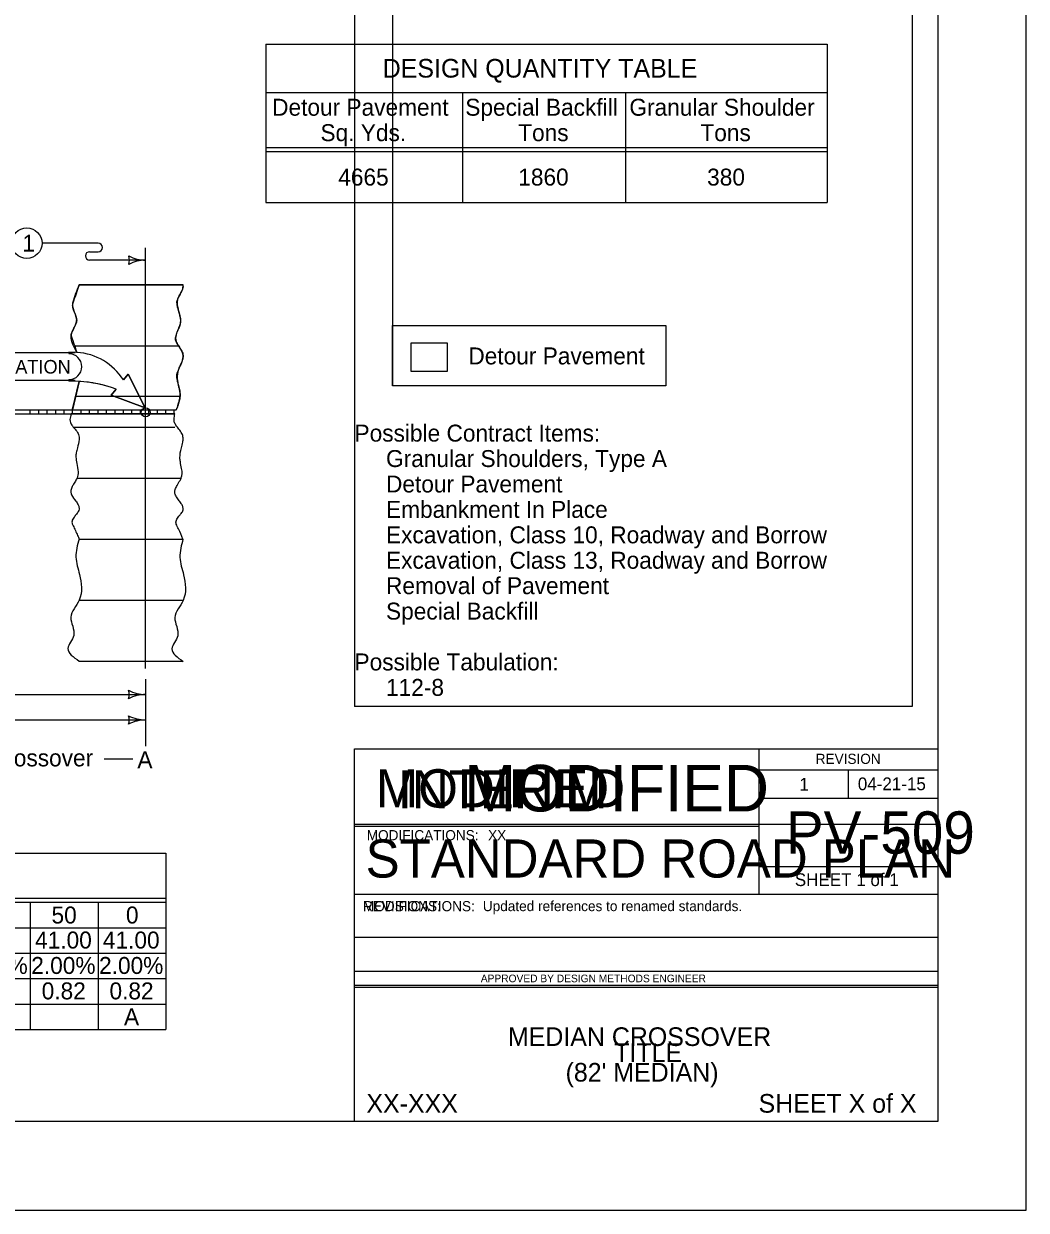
# Model space of a CAD drawing. Extents: x -2135039 to -2131695, y -2139150 to -2136566.
# Drawn here: x -2132878 to -2131695, y -2139150 to -2137750 of the extents above; entities that cross this region are included whole.
import ezdxf

# ---------------------------------------------------------------- set-up
doc = ezdxf.new("R2010")
doc.units = 0
for name, color, linetype in [('dsnDOTLogo', 7, 'Continuous'), ('dsnNonPlotable', 7, 'Continuous'), ('dsnStdBlock', 7, 'Continuous'), ('dsnstdblockInterim', 7, 'Continuous'), ('dsnStdDimension', 7, 'Continuous'), ('dsnStdLabel', 7, 'Continuous'), ('dsnStdLineDrawingWt4', 7, 'Continuous'), ('dsnStdLogo', 7, 'Continuous'), ('dsnstdModifiedBlock', 7, 'Continuous'), ('dsnStdShading', 7, 'Continuous'), ('Level 1', 7, 'Continuous'), ('Level 10', 7, 'Continuous'), ('Level 11', 7, 'Continuous'), ('Level 12', 7, 'Continuous'), ('Level 2', 7, 'Continuous'), ('Level 3', 7, 'Continuous'), ('Level 6', 7, 'Continuous'), ('Level 7', 7, 'Continuous'), ('Level 9', 7, 'Continuous')]:
    doc.layers.add(name, color=color, linetype=linetype)

msp = doc.modelspace()

# ---------------------------------------------------------------- linework, layer by layer
at = {"layer": 'dsnDOTLogo'}
msp.add_lwpolyline([(-2135038.9, -2139150.4), (-2131694.9, -2139150.4), (-2131694.9, -2136566.4), (-2135038.9, -2136566.4)], close=True, dxfattribs=at)
at = {"layer": 'dsnNonPlotable'}
for p, q in [((-2132487.5, -2137085.9), (-2132487.5, -2138555.9)), ((-2131829.4, -2137085.9), (-2131829.4, -2138555.9)), ((-2132442.5, -2137185.9), (-2132442.5, -2138177.5)), ((-2131829.4, -2138555.9), (-2132487.5, -2138555.9))]:
    msp.add_line(p, q, dxfattribs=at)
at = {"layer": 'dsnStdDimension'}
for p, q in [((-2132790, -2138009.4), (-2132856.2, -2138009.4)), ((-2132800, -2138019.4), (-2132790, -2138019.4)), ((-2132733.9, -2138029.4), (-2132800, -2138029.4)), ((-2132734, -2138523.8), (-2132734, -2138602.7)), ((-2132955.1, -2138541.9), (-2132734, -2138541.9)), ((-2133686.9, -2138571.9), (-2132734, -2138571.9)), ((-2132782.7, -2138617.7), (-2132749, -2138617.7))]:
    msp.add_line(p, q, dxfattribs=at)
msp.add_circle((-2132733.9, -2138209.1), 5.33, dxfattribs=at)
for centre, radius, start, end in [((-2132790, -2138014.4), 5, 270, 90), ((-2132800, -2138024.4), 5, 90, 270), ((-2132769.5, -2138029.4), 16.4, 342.2666, 17.7333), ((-2132733.9, -2137986.9), 42.5, 241.9275, 270), ((-2132733.9, -2138071.9), 42.5, 90, 118.0725), ((-2132769.7, -2138541.9), 16.4, 342.2666, 17.7333), ((-2132734, -2138499.4), 42.5, 241.9275, 270), ((-2132734, -2138584.4), 42.5, 90, 118.0725), ((-2132769.7, -2138571.9), 16.4, 342.2666, 17.7333), ((-2132734, -2138529.4), 42.5, 241.9275, 270), ((-2132734, -2138614.4), 42.5, 90, 118.0725)]:
    msp.add_arc(centre, radius, start, end, dxfattribs=at)
at = {"layer": 'dsnStdLabel'}
for p, q in [((-2132817, -2138138.8), (-2133024.5, -2138138.8)), ((-2132815.1, -2138138.3), (-2132824.6, -2138137.9)), ((-2132824.6, -2138137.9), (-2132824.6, -2138139.7)), ((-2132817, -2138171.3), (-2133024.6, -2138171.3)), ((-2132824.6, -2138170.4), (-2132824.6, -2138172.2)), ((-2132754.6, -2138163.8), (-2132760.2, -2138170.8)), ((-2132734.6, -2138203.8), (-2132754.6, -2138163.8)), ((-2132768.7, -2138181.5), (-2132774.6, -2138188.8)), ((-2132774.6, -2138188.8), (-2132734.6, -2138203.8))]:
    msp.add_line(p, q, dxfattribs=at)
for centre, radius, start, end in [((-2132824.6, -2138155.1), 15.3, 270, 90), ((-2132819.6, -2138208.5), 70.4, 32.3953, 86.3054), ((-2132821.8, -2138328.3), 156.1, 70.133, 91.0368)]:
    msp.add_arc(centre, radius, start, end, dxfattribs=at)
at = {"layer": 'dsnStdLineDrawingWt4'}
for p, q in [((-2132812.4, -2138058.5), (-2132689.9, -2138058.5)), ((-2132817.8, -2138130.5), (-2132695.2, -2138130.5)), ((-2132820.1, -2138205.4), (-2132812.3, -2138172.5)), ((-2132816.7, -2138189.7), (-2132694.1, -2138189.7)), ((-2133025.8, -2138206.1), (-2132697.8, -2138206.1)), ((-2133025.8, -2138210.9), (-2132699.5, -2138210.9)), ((-2132870.1, -2138210.9), (-2132870.1, -2138206.1)), ((-2132860.1, -2138210.9), (-2132860.1, -2138206.1)), ((-2132850.1, -2138210.9), (-2132850.1, -2138206.1)), ((-2132840.1, -2138210.9), (-2132840.1, -2138206.1)), ((-2132830.1, -2138210.9), (-2132830.1, -2138206.1)), ((-2132820.1, -2138210.9), (-2132820.1, -2138206.1)), ((-2132810.1, -2138210.9), (-2132810.1, -2138206.1)), ((-2132800.1, -2138210.9), (-2132800.1, -2138206.1)), ((-2132790.1, -2138210.9), (-2132790.1, -2138206.1)), ((-2132780.1, -2138210.9), (-2132780.1, -2138206.1)), ((-2132770.1, -2138210.9), (-2132770.1, -2138206.1)), ((-2132760.1, -2138210.9), (-2132760.1, -2138206.1)), ((-2132750.1, -2138210.9), (-2132750.1, -2138206.1)), ((-2132740.1, -2138210.9), (-2132740.1, -2138206.1)), ((-2132730.1, -2138210.9), (-2132730.1, -2138206.1)), ((-2132720.1, -2138210.9), (-2132720.1, -2138206.1)), ((-2132710.1, -2138210.9), (-2132710.1, -2138206.1)), ((-2132700.1, -2138210.9), (-2132700.1, -2138206.1)), ((-2132818.3, -2138226.5), (-2132699.5, -2138226.5)), ((-2132814.9, -2138286.5), (-2132693, -2138286.5)), ((-2132812.4, -2138358.5), (-2132689.9, -2138358.5)), ((-2132812.4, -2138502.5), (-2132690, -2138502.5))]:
    msp.add_line(p, q, dxfattribs=at)
for points in [[(-2132815, -2138138.4), (-2132821.8, -2138118.9), (-2132821.3, -2138115.7), (-2132818.6, -2138109.7), (-2132816.2, -2138104.6), (-2132815.3, -2138099.8), (-2132816.2, -2138095.6), (-2132819, -2138088), (-2132820.1, -2138082.7), (-2132819.4, -2138078.7), (-2132812.4, -2138058.5)], [(-2132689.7, -2138060.3), (-2132690, -2138062.1), (-2132692.3, -2138067.6), (-2132696.2, -2138075.6), (-2132696.9, -2138080.5), (-2132695.7, -2138087), (-2132694.4, -2138091.5), (-2132692.8, -2138098.6), (-2132693.8, -2138106.6), (-2132695.5, -2138111), (-2132698.5, -2138119.9), (-2132697.4, -2138126.6), (-2132694.9, -2138130.9), (-2132692.1, -2138135.5), (-2132689.9, -2138140.7), (-2132689.9, -2138144.7), (-2132691.8, -2138150.8), (-2132692.6, -2138152.7), (-2132695.9, -2138160.6), (-2132696.4, -2138171.9), (-2132695.1, -2138177.3), (-2132693.7, -2138183.5), (-2132693.5, -2138191.6), (-2132694.8, -2138197.1), (-2132696.6, -2138202.8)], [(-2132689.7, -2138060.3), (-2132689.7, -2138059.2), (-2132689.8, -2138058.7), (-2132689.9, -2138058.5)], [(-2132696.5, -2138202.8), (-2132697.2, -2138204.6), (-2132697.8, -2138206.1)], [(-2132821.7, -2138210.9), (-2132823.2, -2138217.5), (-2132822.7, -2138220.9), (-2132820.3, -2138225), (-2132816.2, -2138230.1), (-2132813, -2138235.3), (-2132812.5, -2138241), (-2132814.5, -2138250.8), (-2132815.9, -2138256.9), (-2132816.2, -2138261.7), (-2132815.2, -2138269.3), (-2132813.7, -2138279.2), (-2132813.8, -2138283.1), (-2132816.2, -2138289.1), (-2132819, -2138293.8), (-2132821, -2138297.6), (-2132822.2, -2138302.6), (-2132821.3, -2138306.3), (-2132816.4, -2138313.7), (-2132813.6, -2138318.1), (-2132812.5, -2138321.6), (-2132812.9, -2138324.8), (-2132815.5, -2138329.1), (-2132818.3, -2138332.6), (-2132820, -2138335.1), (-2132820.8, -2138337.4), (-2132820.7, -2138339.6), (-2132819.4, -2138342.8), (-2132816.9, -2138348.3), (-2132814.2, -2138354.4), (-2132812.4, -2138358.5)], [(-2132689.9, -2138358.5), (-2132695.2, -2138346.5), (-2132697.8, -2138340.8), (-2132698.2, -2138338.5), (-2132696.4, -2138334), (-2132694.6, -2138331.6), (-2132692, -2138328.2), (-2132689.8, -2138324), (-2132690.2, -2138320.1), (-2132692, -2138316.6), (-2132695.1, -2138312.1), (-2132698.1, -2138307.7), (-2132699.5, -2138303.5), (-2132699.1, -2138300.1), (-2132696.8, -2138295.1), (-2132693.4, -2138289.3), (-2132691.9, -2138286), (-2132691, -2138281.8), (-2132691.5, -2138275.3), (-2132693, -2138267.3), (-2132693.5, -2138262.6), (-2132691.8, -2138251), (-2132690.2, -2138244.2), (-2132689.7, -2138239), (-2132691.2, -2138233.9), (-2132694.7, -2138228.9), (-2132698.3, -2138224), (-2132700.2, -2138220), (-2132700.4, -2138217.2), (-2132699.5, -2138210.9)], [(-2132812.4, -2138358.5), (-2132816.2, -2138379.7), (-2132811.9, -2138400.3), (-2132812.4, -2138430.5), (-2132822.2, -2138450.8), (-2132818.8, -2138472.2), (-2132825.6, -2138487.6), (-2132812.4, -2138502.5)], [(-2132689.9, -2138358.5), (-2132693.5, -2138380.1), (-2132689.2, -2138400.6), (-2132689.7, -2138430.8), (-2132699.5, -2138451.1), (-2132696.1, -2138472.5), (-2132702.9, -2138487.9), (-2132689.7, -2138502.8)]]:
    msp.add_spline(points, degree=3, dxfattribs=at)
at = {"layer": 'dsnStdLogo'}
for p, q in [((-2132010.4, -2138605.9), (-2132010.4, -2138697.3)), ((-2132010.4, -2138630.9), (-2131799.4, -2138630.9)), ((-2131904.9, -2138630.9), (-2131904.9, -2138664.1)), ((-2132010.4, -2138664.1), (-2131799.4, -2138664.1)), ((-2132487.5, -2138697.3), (-2132010.4, -2138697.3)), ((-2132010.4, -2138697.3), (-2132010.4, -2138777.3)), ((-2131799.4, -2138745.1), (-2132010.4, -2138745.1)), ((-2132487.5, -2138777.3), (-2131799.4, -2138777.3)), ((-2132487.5, -2138828.3), (-2131799.4, -2138828.3)), ((-2132487.5, -2138868.3), (-2131799.4, -2138868.3)), ((-2132487.5, -2138887.3), (-2131799.4, -2138887.3))]:
    msp.add_line(p, q, dxfattribs=at)
msp.add_lwpolyline([(-2132487.5, -2138605.9), (-2131799.4, -2138605.9), (-2131799.4, -2139045.9), (-2132487.5, -2139045.9)], close=True, dxfattribs=at)
at = {"layer": 'dsnstdModifiedBlock'}
for p, q in [((-2132487.5, -2138695), (-2131799.4, -2138695)), ((-2132487.5, -2138885), (-2131799.4, -2138885))]:
    msp.add_line(p, q, dxfattribs=at)
msp.add_lwpolyline([(-2132487.5, -2138605.9), (-2131799.4, -2138605.9), (-2131799.4, -2139045.9), (-2132487.5, -2139045.9)], close=True, dxfattribs=at)
at = {"layer": 'dsnStdShading'}
for p, q in [((-2132689.9, -2138058.5), (-2132812.4, -2138058.5)), ((-2132420.7, -2138126.9), (-2132378.1, -2138126.9)), ((-2132420.7, -2138160.6), (-2132420.7, -2138126.9)), ((-2132378.1, -2138126.9), (-2132378.1, -2138160.6)), ((-2132378.1, -2138160.6), (-2132420.7, -2138160.6)), ((-2132812.3, -2138172.5), (-2132820.3, -2138206.1)), ((-2132760.2, -2138170.8), (-2132754.6, -2138163.8)), ((-2132754.6, -2138163.8), (-2132734.6, -2138203.8)), ((-2132774.6, -2138188.8), (-2132768.7, -2138181.5)), ((-2132734.6, -2138203.8), (-2132774.6, -2138188.8)), ((-2132812.4, -2138358.5), (-2132689.9, -2138358.5))]:
    msp.add_line(p, q, dxfattribs=at)
for points in [[(-2132699.5, -2138210.9), (-2132700.1, -2138210.9), (-2132710.1, -2138210.9), (-2132720.1, -2138210.9), (-2132730.1, -2138210.9), (-2132740.1, -2138210.9), (-2132750.1, -2138210.9), (-2132760.1, -2138210.9), (-2132770.1, -2138210.9), (-2132780.1, -2138210.9), (-2132790.1, -2138210.9), (-2132800.1, -2138210.9), (-2132810.1, -2138210.9), (-2132820.1, -2138210.9), (-2132821.7, -2138210.9)], [(-2132820.3, -2138206.1), (-2132820.1, -2138206.1), (-2132810.1, -2138206.1), (-2132800.1, -2138206.1), (-2132790.1, -2138206.1), (-2132780.1, -2138206.1), (-2132770.1, -2138206.1), (-2132760.1, -2138206.1), (-2132750.1, -2138206.1), (-2132740.1, -2138206.1), (-2132730.1, -2138206.1), (-2132720.1, -2138206.1), (-2132710.1, -2138206.1), (-2132700.1, -2138206.1), (-2132697.8, -2138206.1)]]:
    msp.add_lwpolyline(points, dxfattribs=at)
for centre, radius, start, end in [((-2132819.6, -2138208.5), 70.4, 32.3953, 86.258), ((-2132821.8, -2138328.3), 156.1, 70.133, 86.5437)]:
    msp.add_arc(centre, radius, start, end, dxfattribs=at)
for points in [[(-2132812.4, -2138058.5), (-2132814.7, -2138065.2), (-2132817.1, -2138072), (-2132819.4, -2138078.7), (-2132819.9, -2138080), (-2132820.2, -2138081.4), (-2132820.1, -2138082.7), (-2132820.1, -2138084.5), (-2132819.5, -2138086.3), (-2132819, -2138088), (-2132818.2, -2138090.6), (-2132817, -2138093), (-2132816.2, -2138095.6), (-2132815.7, -2138097), (-2132815.4, -2138098.4), (-2132815.3, -2138099.8), (-2132815.3, -2138101.4), (-2132815.5, -2138103), (-2132816.2, -2138104.6), (-2132817, -2138106.4), (-2132817.8, -2138108), (-2132818.6, -2138109.7), (-2132819.6, -2138111.7), (-2132820.5, -2138113.7), (-2132821.3, -2138115.7), (-2132821.8, -2138116.7), (-2132822.1, -2138117.9), (-2132821.8, -2138118.9), (-2132819.5, -2138125.4), (-2132817.3, -2138131.8), (-2132815, -2138138.3)], [(-2132696.5, -2138202.8), (-2132696, -2138200.9), (-2132695.4, -2138199), (-2132694.8, -2138197.1), (-2132694.3, -2138195.3), (-2132693.8, -2138193.4), (-2132693.5, -2138191.6), (-2132693, -2138188.9), (-2132693.2, -2138186.1), (-2132693.7, -2138183.5), (-2132694.1, -2138181.4), (-2132694.6, -2138179.3), (-2132695.1, -2138177.3), (-2132695.5, -2138175.5), (-2132696, -2138173.7), (-2132696.4, -2138171.9), (-2132697.2, -2138168.2), (-2132697.3, -2138164.1), (-2132695.9, -2138160.6), (-2132694.8, -2138158), (-2132693.7, -2138155.3), (-2132692.6, -2138152.7), (-2132692.3, -2138152.1), (-2132692, -2138151.4), (-2132691.8, -2138150.8), (-2132690.9, -2138148.8), (-2132690.4, -2138146.8), (-2132689.9, -2138144.7), (-2132689.6, -2138143.4), (-2132689.6, -2138142), (-2132689.9, -2138140.7), (-2132690.4, -2138138.9), (-2132691.1, -2138137.1), (-2132692.1, -2138135.5), (-2132693, -2138134), (-2132694, -2138132.5), (-2132694.9, -2138130.9), (-2132695.8, -2138129.5), (-2132696.6, -2138128.1), (-2132697.4, -2138126.6), (-2132698.5, -2138124.5), (-2132699.1, -2138122), (-2132698.5, -2138119.9), (-2132697.7, -2138116.9), (-2132696.6, -2138113.9), (-2132695.5, -2138111), (-2132695, -2138109.5), (-2132694.3, -2138108.1), (-2132693.8, -2138106.6), (-2132692.9, -2138104), (-2132692.4, -2138101.2), (-2132692.8, -2138098.6), (-2132693.2, -2138096.2), (-2132693.7, -2138093.9), (-2132694.4, -2138091.5), (-2132694.8, -2138090), (-2132695.3, -2138088.5), (-2132695.7, -2138087), (-2132696.3, -2138084.8), (-2132696.7, -2138082.6), (-2132696.9, -2138080.5), (-2132697.1, -2138078.9), (-2132696.9, -2138077.2), (-2132696.2, -2138075.6), (-2132695, -2138072.7), (-2132693.5, -2138070.3), (-2132692.3, -2138067.6), (-2132691.5, -2138065.8), (-2132690.3, -2138064.1), (-2132690, -2138062.1), (-2132689.9, -2138061.5), (-2132689.8, -2138060.9), (-2132689.7, -2138060.3)], [(-2132697.8, -2138206.1), (-2132697.6, -2138205.6), (-2132697.4, -2138205.1), (-2132697.2, -2138204.6), (-2132697, -2138204), (-2132696.8, -2138203.4), (-2132696.5, -2138202.8)]]:
    msp.add_open_spline(points, degree=3, dxfattribs=at)
for points in [[(-2132689.7, -2138060.3), (-2132689.7, -2138059.2), (-2132689.8, -2138058.7), (-2132689.9, -2138058.5)], [(-2132821.7, -2138210.9), (-2132823.2, -2138217.5), (-2132822.7, -2138220.9), (-2132820.3, -2138225), (-2132816.2, -2138230.1), (-2132813, -2138235.3), (-2132812.5, -2138241), (-2132814.5, -2138250.8), (-2132815.9, -2138256.9), (-2132816.2, -2138261.7), (-2132815.2, -2138269.3), (-2132813.7, -2138279.2), (-2132813.8, -2138283.1), (-2132816.2, -2138289.1), (-2132819, -2138293.8), (-2132821, -2138297.6), (-2132822.2, -2138302.6), (-2132821.3, -2138306.3), (-2132816.4, -2138313.7), (-2132813.6, -2138318.1), (-2132812.5, -2138321.6), (-2132812.9, -2138324.8), (-2132815.5, -2138329.1), (-2132818.3, -2138332.6), (-2132820, -2138335.1), (-2132820.8, -2138337.4), (-2132820.7, -2138339.6), (-2132819.4, -2138342.8), (-2132816.9, -2138348.3), (-2132814.2, -2138354.4), (-2132812.4, -2138358.5)], [(-2132689.9, -2138358.5), (-2132695.2, -2138346.5), (-2132697.8, -2138340.8), (-2132698.2, -2138338.5), (-2132696.4, -2138334), (-2132694.6, -2138331.6), (-2132692, -2138328.2), (-2132689.8, -2138324), (-2132690.2, -2138320.1), (-2132692, -2138316.6), (-2132695.1, -2138312.1), (-2132698.1, -2138307.7), (-2132699.5, -2138303.5), (-2132699.1, -2138300.1), (-2132696.8, -2138295.1), (-2132693.4, -2138289.3), (-2132691.9, -2138286), (-2132691, -2138281.8), (-2132691.5, -2138275.3), (-2132693, -2138267.3), (-2132693.5, -2138262.6), (-2132691.8, -2138251), (-2132690.2, -2138244.2), (-2132689.7, -2138239), (-2132691.2, -2138233.9), (-2132694.7, -2138228.9), (-2132698.3, -2138224), (-2132700.2, -2138220), (-2132700.4, -2138217.2), (-2132699.5, -2138210.9)]]:
    msp.add_spline(points, degree=3, dxfattribs=at)
at = {"layer": 'Level 1'}
msp.add_line((-2132592.2, -2137831.6), (-2131930, -2137831.6), dxfattribs=at)
msp.add_lwpolyline([(-2134934.4, -2137035.9), (-2131799.4, -2137035.9), (-2131799.4, -2139045.9), (-2134934.4, -2139045.9)], close=True, dxfattribs=at)
at = {"layer": 'Level 10'}
msp.add_circle((-2132874.2, -2138009.4), 18, dxfattribs=at)
at = {"layer": 'Level 11'}
for p, q in [((-2134872.5, -2138729.1), (-2132710.1, -2138729.1)), ((-2132710.1, -2138729.1), (-2132710.1, -2138937.1)), ((-2134872.5, -2138937.1), (-2132710.1, -2138937.1))]:
    msp.add_line(p, q, dxfattribs=at)
at = {"layer": 'Level 12'}
for p, q in [((-2132592.2, -2137774.4), (-2132592.2, -2137961.4)), ((-2132592.2, -2137774.4), (-2131930, -2137774.4)), ((-2131930, -2137774.4), (-2131930, -2137961.4)), ((-2132592.2, -2137961.4), (-2131930, -2137961.4))]:
    msp.add_line(p, q, dxfattribs=at)
msp.add_lwpolyline([(-2132442.5, -2138106.6), (-2132120.3, -2138106.6), (-2132120.3, -2138177.5), (-2132442.5, -2138177.5)], close=True, dxfattribs=at)
at = {"layer": 'Level 2'}
for p, q in [((-2132360.1, -2137831.6), (-2132360.1, -2137961.4)), ((-2132167.7, -2137831.6), (-2132167.7, -2137961.4)), ((-2132167.7, -2137831.6), (-2132167.7, -2137961.4)), ((-2132592.2, -2137896.4), (-2131930, -2137896.4)), ((-2132592.2, -2137901.4), (-2131930, -2137901.4)), ((-2132420.7, -2138126.9), (-2132378.1, -2138126.9)), ((-2132420.7, -2138160.6), (-2132420.7, -2138126.9)), ((-2132378.1, -2138126.9), (-2132378.1, -2138160.6)), ((-2132378.1, -2138160.6), (-2132420.7, -2138160.6)), ((-2134872.5, -2138782.1), (-2132710.1, -2138782.1)), ((-2134872.5, -2138787.1), (-2132710.1, -2138787.1)), ((-2132870.1, -2138787.1), (-2132870.1, -2138937.1)), ((-2132790.1, -2138787.1), (-2132790.1, -2138937.1))]:
    msp.add_line(p, q, dxfattribs=at)
at = {"layer": 'Level 3'}
for p, q in [((-2132734, -2138511.4), (-2132734, -2138014.9)), ((-2132812.4, -2138430.5), (-2132689.6, -2138430.5))]:
    msp.add_line(p, q, dxfattribs=at)
at = {"layer": 'Level 9'}
for p, q in [((-2134872.5, -2138817.1), (-2132710.1, -2138817.1)), ((-2134872.5, -2138847.1), (-2132710.1, -2138847.1)), ((-2134872.5, -2138877.1), (-2132710.1, -2138877.1)), ((-2134872.5, -2138907.1), (-2132710.1, -2138907.1))]:
    msp.add_line(p, q, dxfattribs=at)

# ---------------------------------------------------------------- texts
at = {"layer": 'dsnNonPlotable'}
msp.add_text('REVISIONS:', height=12, dxfattribs=at).set_placement((-2132477.5, -2138797.6))
at = {"layer": 'dsnStdBlock'}
for s, height, p in [('MODIFIED', 45, (-2132462.4, -2138675.1)), ('MODIFICATIONS:', 12, (-2132477.5, -2138797.6))]:
    msp.add_text(s, height=height, dxfattribs=at).set_placement(p)
at = {"layer": 'dsnstdblockInterim'}
msp.add_text('INTERIM', height=45, dxfattribs=at).set_placement((-2132436.5, -2138676.3))
at = {"layer": 'dsnStdLabel'}
msp.add_text('LOCATION STATION', height=16, dxfattribs=at).set_placement((-2133030.4, -2138163.2))
at = {"layer": 'dsnStdLogo'}
for s, height, p in [('REVISION', 12, (-2131943.4, -2138623.8)), ('04-21-15', 15, (-2131893.7, -2138654.8)), ('1', 15, (-2131962.6, -2138655.3)), ('PV-509', 50, (-2131978.6, -2138729.8)), ('STANDARD ROAD PLAN', 45.001, (-2132474.4, -2138757.9)), ('SHEET 1 of 1', 15, (-2131968, -2138767.9)), ('Updated references to renamed standards.', 12, (-2132336.1, -2138797.5)), ('APPROVED BY DESIGN METHODS ENGINEER', 9.003, (-2132338.5, -2138881.4)), ('MEDIAN CROSSOVER', 22, (-2132306.5, -2138956.6)), ("(82' MEDIAN)", 22, (-2132238.5, -2138998.6))]:
    msp.add_text(s, height=height, dxfattribs=at).set_placement(p)
at = {"layer": 'dsnstdModifiedBlock'}
for s, height, p in [('MODIFIED', 55, (-2132358.1, -2138679.9)), ('MODIFICATIONS:', 12, (-2132473.1, -2138713.9)), ('XX', 12, (-2132329.9, -2138713.9)), ('TITLE', 22, (-2132181.1, -2138975.4)), ('XX-XXX', 22, (-2132473.5, -2139035.3)), ('SHEET X of X', 22, (-2132010.8, -2139035.3))]:
    msp.add_text(s, height=height, dxfattribs=at).set_placement(p)
at = {"layer": 'Level 1'}
for s, p in [('Possible Contract Items:', (-2132487.5, -2138243.5)), ('     Granular Shoulders, Type A', (-2132487.5, -2138273.5)), ('     Detour Pavement', (-2132487.5, -2138303.5)), ('     Embankment In Place', (-2132487.5, -2138333.5)), ('     Excavation, Class 10, Roadway and Borrow', (-2132487.5, -2138363.5)), ('     Excavation, Class 13, Roadway and Borrow', (-2132487.5, -2138393.5)), ('     Removal of Pavement', (-2132487.5, -2138423.5)), ('     Special Backfill', (-2132487.5, -2138453.5)), ('Possible Tabulation:', (-2132487.5, -2138513.5)), ('     112-8', (-2132487.5, -2138543.5))]:
    msp.add_text(s, height=20, dxfattribs=at).set_placement(p)
at = {"layer": 'Level 6'}
msp.add_text('DESIGN QUANTITY TABLE', height=22, dxfattribs=at).set_placement((-2132454.2, -2137814))
at = {"layer": 'Level 7'}
for s, p in [('Detour Pavement', (-2132584.7, -2137859)), ('Special Backfill', (-2132356.8, -2137859)), ('Granular Shoulder', (-2132163.2, -2137859)), ('Sq. Yds.', (-2132527.7, -2137889)), ('Tons', (-2132294.4, -2137889)), ('Tons', (-2132079.4, -2137889)), ('4665', (-2132506.7, -2137941.4)), ('1860', (-2132294.3, -2137941.4)), ('380', (-2132071.5, -2137941.4)), ('1', (-2132879.4, -2138019.4)), ('Detour Pavement', (-2132353.2, -2138152.4)), (' of Crossover', (-2132954.9, -2138626.7)), ('A', (-2132743.7, -2138628.9)), ('50', (-2132845, -2138812.1)), ('0', (-2132757.2, -2138812.1)), ('41.00', (-2132864.4, -2138841.6)), ('41.00', (-2132784.4, -2138841.6)), ('2.00%', (-2132948.9, -2138871.6)), ('2.00%', (-2132868.9, -2138871.6)), ('2.00%', (-2132788.9, -2138871.6)), ('0.82', (-2132856.6, -2138901.6)), ('0.82', (-2132776.6, -2138901.6)), ('A', (-2132759.5, -2138932.1))]:
    msp.add_text(s, height=20, dxfattribs=at).set_placement(p)

doc.saveas('drawing.dxf')
